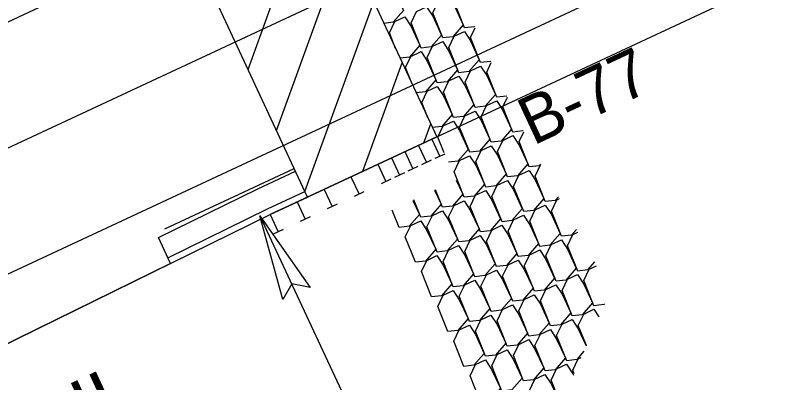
# Model space of a CAD drawing. Extents: x 2320644 to 2322941, y 921672 to 923041.
# Drawn here: x 2321563.6 to 2321644, y 922124.4 to 922163 of the extents above; entities that cross this region are included whole.
import ezdxf

# ---------------------------------------------------------------- set-up
doc = ezdxf.new("R2010")
doc.units = 0
for name, color, linetype in [('Matchline', 7, 'Continuous'), ('Prop Approach Slab', 7, 'Continuous'), ('Prop Approach Slab Hatching', 7, 'Continuous'), ('Prop Conc Shoulder Berm Gutter', 7, 'Continuous'), ('Prop EOT', 7, 'Continuous'), ('Prop Guardrail', 7, 'Continuous'), ('Prop Horizontal Alignment Tick Large', 7, 'Continuous'), ('Prop North Arrow NAD83 for Plan Sheets CELL', 7, 'Continuous'), ('Prop Structure Anchor Unit CELL', 7, 'Continuous'), ('Sheet Profile Grid Major CELL', 7, 'Continuous'), ('Sheet Profile Grid Minor CELL', 7, 'Continuous'), ('Skimmer Basin Note Both CELL', 7, 'Continuous')]:
    doc.layers.add(name, color=color, linetype=linetype)

msp = doc.modelspace()

# ---------------------------------------------------------------- linework, layer by layer
at = {"layer": 'Matchline'}
msp.add_line((2321411.134, 922078.361), (2321804.398, 922261.67), dxfattribs=at)
at = {"layer": 'Prop Approach Slab'}
for p, q in [((2321406.064, 922089.237), (2321799.328, 922272.547)), ((2321416.203, 922067.484), (2321809.467, 922250.794)), ((2321594.298, 922143.879), (2321579.089, 922176.508)), ((2321607.894, 922150.216), (2321594.298, 922143.879))]:
    msp.add_line(p, q, dxfattribs=at)
at = {"layer": 'Prop Approach Slab Hatching'}
for p, q in [((2321588.051, 922157.281), (2321595.31, 922177.214)), ((2321591.039, 922150.872), (2321598.297, 922170.805)), ((2321594.026, 922144.463), (2321601.284, 922164.396)), ((2321600.123, 922146.594), (2321604.272, 922157.987)), ((2321606.532, 922149.581), (2321607.259, 922151.578))]:
    msp.add_line(p, q, dxfattribs=at)
at = {"layer": 'Prop Conc Shoulder Berm Gutter'}
for p, q in [((2321590.381, 922142.053), (2321607.894, 922150.216)), ((2321589.087, 922144.759), (2321593.031, 922146.598)), ((2321578.628, 922139.627), (2321589.087, 922144.759)), ((2321579.896, 922136.908), (2321578.628, 922139.627)), ((2321579.896, 922136.908), (2321500.589, 922097.992))]:
    msp.add_line(p, q, dxfattribs=at)
at = {"layer": 'Prop Guardrail'}
msp.add_line((2321500.589, 922097.992), (2321590.381, 922142.053), dxfattribs=at)
at = {"layer": 'Prop Horizontal Alignment Tick Large'}
for p, q in [((2321607.894, 922150.216), (2321798.232, 922238.937)), ((2321592.685, 922182.845), (2321607.894, 922150.216))]:
    msp.add_line(p, q, dxfattribs=at)
at = {"layer": 'Prop Structure Anchor Unit CELL'}
for p, q in [((2321607.376, 922149.974), (2321590.381, 922142.053)), ((2321607.376, 922149.974), (2321608.221, 922148.161)), ((2321605.959, 922149.314), (2321606.804, 922147.501)), ((2321604.543, 922148.654), (2321605.388, 922146.841)), ((2321608.74, 922148.403), (2321607.701, 922147.92)), ((2321603.127, 922147.994), (2321603.972, 922146.181)), ((2321607.323, 922147.743), (2321606.285, 922147.259)), ((2321601.711, 922147.334), (2321602.556, 922145.521)), ((2321605.907, 922147.083), (2321604.869, 922146.599)), ((2321598.878, 922146.013), (2321599.723, 922144.201)), ((2321604.491, 922146.423), (2321603.453, 922145.939)), ((2321603.075, 922145.763), (2321602.037, 922145.279)), ((2321596.046, 922144.693), (2321596.891, 922142.88)), ((2321600.242, 922144.443), (2321599.204, 922143.959)), ((2321593.214, 922143.373), (2321594.059, 922141.56)), ((2321597.41, 922143.122), (2321596.372, 922142.639)), ((2321590.381, 922142.053), (2321591.226, 922140.24)), ((2321594.578, 922141.802), (2321593.539, 922141.318)), ((2321591.745, 922140.482), (2321590.707, 922139.998))]:
    msp.add_line(p, q, dxfattribs=at)
at = {"layer": 'Sheet Profile Grid Major CELL'}
msp.add_line((2321624.408, 922132.096), (2321624.927, 922131.292), dxfattribs=at)
for points in [[(2321602.848, 922166.455), (2321603.492, 922165.458), (2321604.411, 922163.487), (2321603.325, 922162.236), (2321602.342, 922162.127)], [(2321611.875, 922161.793), (2321611.858, 922161.772), (2321610.809, 922161.656), (2321609.752, 922164.308), (2321610.232, 922165.319)], [(2321609.103, 922164.929), (2321609.747, 922163.933), (2321610.666, 922161.962), (2321609.58, 922160.711), (2321608.531, 922160.594), (2321607.475, 922163.246), (2321608.038, 922164.433), (2321609.103, 922164.929)], [(2321606.826, 922163.868), (2321607.47, 922162.872), (2321608.389, 922160.9), (2321607.303, 922159.649), (2321606.254, 922159.533), (2321605.197, 922162.185), (2321605.761, 922163.372), (2321606.826, 922163.868)], [(2321603.57, 922159.491), (2321602.92, 922161.123), (2321603.484, 922162.31), (2321604.549, 922162.806)], [(2321604.549, 922162.806), (2321605.193, 922161.81), (2321606.111, 922159.839), (2321605.026, 922158.588), (2321604.042, 922158.479)], [(2321610.804, 922161.281), (2321611.448, 922160.285), (2321612.366, 922158.314), (2321611.281, 922157.063), (2321610.232, 922156.946), (2321609.175, 922159.598), (2321609.739, 922160.785), (2321610.804, 922161.281)], [(2321613.576, 922158.145), (2321613.558, 922158.124), (2321612.509, 922158.008), (2321611.452, 922160.659), (2321611.933, 922161.67)], [(2321608.527, 922160.22), (2321609.17, 922159.223), (2321610.089, 922157.252), (2321609.003, 922156.001), (2321607.955, 922155.885), (2321606.898, 922158.537), (2321607.462, 922159.723), (2321608.527, 922160.22)], [(2321605.271, 922155.843), (2321604.62, 922157.475), (2321605.184, 922158.662), (2321606.249, 922159.158)], [(2321606.249, 922159.158), (2321606.893, 922158.162), (2321607.812, 922156.191), (2321606.726, 922154.94), (2321605.743, 922154.83)], [(2321615.276, 922154.497), (2321615.258, 922154.476), (2321614.21, 922154.36), (2321613.153, 922157.011), (2321613.633, 922158.022)], [(2321612.504, 922157.633), (2321613.148, 922156.637), (2321614.067, 922154.665), (2321612.981, 922153.415), (2321611.932, 922153.298), (2321610.875, 922155.95), (2321611.439, 922157.137), (2321612.504, 922157.633)], [(2321610.227, 922156.572), (2321610.871, 922155.575), (2321611.79, 922153.604), (2321610.704, 922152.353), (2321609.655, 922152.237), (2321608.598, 922154.888), (2321609.162, 922156.075), (2321610.227, 922156.572)], [(2321606.971, 922152.195), (2321606.321, 922153.827), (2321606.885, 922155.014), (2321607.95, 922155.51)], [(2321607.95, 922155.51), (2321608.594, 922154.514), (2321609.512, 922152.542), (2321608.427, 922151.292), (2321607.443, 922151.182)], [(2321614.205, 922153.985), (2321614.849, 922152.989), (2321615.767, 922151.017), (2321614.682, 922149.766), (2321613.633, 922149.65), (2321612.576, 922152.302), (2321613.14, 922153.489), (2321614.205, 922153.985)], [(2321616.977, 922150.849), (2321616.959, 922150.828), (2321615.91, 922150.711), (2321614.853, 922153.363), (2321615.334, 922154.374)], [(2321611.928, 922152.923), (2321612.571, 922151.927), (2321613.49, 922149.956), (2321612.404, 922148.705), (2321611.356, 922148.588), (2321610.299, 922151.24), (2321610.863, 922152.427), (2321611.928, 922152.923)], [(2321608.672, 922148.547), (2321608.021, 922150.179), (2321608.585, 922151.366), (2321609.65, 922151.862)], [(2321609.65, 922151.862), (2321610.294, 922150.866), (2321611.213, 922148.894), (2321610.127, 922147.643), (2321609.144, 922147.534)], [(2321618.79, 922147.33), (2321618.659, 922147.18), (2321617.611, 922147.063), (2321616.554, 922149.715), (2321617.034, 922150.726)], [(2321615.905, 922150.337), (2321616.549, 922149.34), (2321617.468, 922147.369), (2321616.382, 922146.118), (2321615.333, 922146.002), (2321614.276, 922148.654), (2321614.84, 922149.84), (2321615.905, 922150.337)], [(2321613.628, 922149.275), (2321614.272, 922148.279), (2321615.191, 922146.308), (2321614.105, 922145.057), (2321613.056, 922144.94), (2321611.999, 922147.592), (2321612.563, 922148.779), (2321613.628, 922149.275)], [(2321611.351, 922148.214), (2321611.995, 922147.218), (2321612.913, 922145.246), (2321611.828, 922143.995), (2321610.779, 922143.879), (2321609.722, 922146.531), (2321610.286, 922147.717), (2321611.351, 922148.214)], [(2321617.606, 922146.689), (2321618.25, 922145.692), (2321619.168, 922143.721), (2321618.083, 922142.47), (2321617.034, 922142.354), (2321615.977, 922145.005), (2321616.541, 922146.192), (2321617.606, 922146.689)], [(2321620.688, 922143.91), (2321620.36, 922143.532), (2321619.311, 922143.415), (2321618.254, 922146.067), (2321618.818, 922147.254), (2321618.829, 922147.259)], [(2321609.95, 922145.658), (2321610.636, 922144.185), (2321609.55, 922142.934), (2321608.501, 922142.817), (2321607.774, 922144.643)], [(2321615.329, 922145.627), (2321615.972, 922144.631), (2321616.891, 922142.659), (2321615.805, 922141.409), (2321614.756, 922141.292), (2321613.7, 922143.944), (2321614.264, 922145.131), (2321615.329, 922145.627)], [(2321607.672, 922144.596), (2321608.359, 922143.123), (2321607.273, 922141.872), (2321606.224, 922141.756), (2321605.497, 922143.582)], [(2321613.051, 922144.566), (2321613.695, 922143.569), (2321614.614, 922141.598), (2321613.528, 922140.347), (2321612.479, 922140.231), (2321611.422, 922142.882), (2321611.986, 922144.069), (2321613.051, 922144.566)], [(2321605.395, 922143.535), (2321606.082, 922142.062), (2321604.996, 922140.811), (2321603.947, 922140.694), (2321603.219, 922142.52)], [(2321610.774, 922143.504), (2321611.418, 922142.508), (2321612.337, 922140.537), (2321611.251, 922139.286), (2321610.202, 922139.169), (2321609.145, 922141.821), (2321609.709, 922143.008), (2321610.774, 922143.504)], [(2321622.587, 922140.49), (2321622.06, 922139.884), (2321621.011, 922139.767), (2321619.955, 922142.419), (2321620.519, 922143.606), (2321620.788, 922143.731)], [(2321619.306, 922143.041), (2321619.95, 922142.044), (2321620.869, 922140.073), (2321619.783, 922138.822), (2321618.734, 922138.705), (2321617.677, 922141.357), (2321618.241, 922142.544), (2321619.306, 922143.041)], [(2321608.497, 922142.443), (2321609.14, 922141.446), (2321610.059, 922139.475), (2321608.974, 922138.224), (2321607.925, 922138.108), (2321606.868, 922140.759), (2321607.432, 922141.946), (2321608.497, 922142.443)], [(2321617.029, 922141.979), (2321617.673, 922140.983), (2321618.592, 922139.011), (2321617.506, 922137.761), (2321616.457, 922137.644), (2321615.4, 922140.296), (2321615.964, 922141.483), (2321617.029, 922141.979)], [(2321606.22, 922141.381), (2321606.863, 922140.385), (2321607.782, 922138.414), (2321606.696, 922137.163), (2321605.647, 922137.046), (2321604.591, 922139.698), (2321605.155, 922140.885), (2321606.22, 922141.381)], [(2321614.752, 922140.918), (2321615.395, 922139.921), (2321616.314, 922137.95), (2321615.229, 922136.699), (2321614.18, 922136.582), (2321613.123, 922139.234), (2321613.687, 922140.421), (2321614.752, 922140.918)], [(2321612.475, 922139.856), (2321613.118, 922138.86), (2321614.037, 922136.888), (2321612.951, 922135.638), (2321611.902, 922135.521), (2321610.846, 922138.173), (2321611.41, 922139.36), (2321612.475, 922139.856)], [(2321624.485, 922137.07), (2321623.761, 922136.235), (2321622.712, 922136.119), (2321621.655, 922138.771), (2321622.219, 922139.957), (2321622.746, 922140.203)], [(2321610.197, 922138.795), (2321610.841, 922137.798), (2321611.76, 922135.827), (2321610.674, 922134.576), (2321609.625, 922134.46), (2321608.568, 922137.111), (2321609.132, 922138.298), (2321610.197, 922138.795)], [(2321621.007, 922139.392), (2321621.65, 922138.396), (2321622.569, 922136.425), (2321621.484, 922135.174), (2321620.435, 922135.057), (2321619.378, 922137.709), (2321619.942, 922138.896), (2321621.007, 922139.392)], [(2321618.73, 922138.331), (2321619.373, 922137.335), (2321620.292, 922135.363), (2321619.206, 922134.112), (2321618.157, 922133.996), (2321617.101, 922136.648), (2321617.665, 922137.834), (2321618.73, 922138.331)], [(2321607.92, 922137.733), (2321608.564, 922136.737), (2321609.483, 922134.765), (2321608.397, 922133.515), (2321607.348, 922133.398), (2321606.291, 922136.05), (2321606.855, 922137.237), (2321607.92, 922137.733)], [(2321616.452, 922137.269), (2321617.096, 922136.273), (2321618.015, 922134.302), (2321616.929, 922133.051), (2321615.88, 922132.934), (2321614.823, 922135.586), (2321615.387, 922136.773), (2321616.452, 922137.269)], [(2321614.175, 922136.208), (2321614.819, 922135.212), (2321615.738, 922133.24), (2321614.652, 922131.989), (2321613.603, 922131.873), (2321612.546, 922134.525), (2321613.11, 922135.712), (2321614.175, 922136.208)], [(2321625.515, 922132.649), (2321625.461, 922132.587), (2321624.412, 922132.471), (2321623.356, 922135.122), (2321623.92, 922136.309), (2321624.704, 922136.675)], [(2321622.707, 922135.744), (2321623.351, 922134.748), (2321624.27, 922132.777), (2321623.184, 922131.526), (2321622.135, 922131.409), (2321621.078, 922134.061), (2321621.642, 922135.248), (2321622.707, 922135.744)], [(2321611.898, 922135.146), (2321612.541, 922134.15), (2321613.46, 922132.179), (2321612.375, 922130.928), (2321611.326, 922130.811), (2321610.269, 922133.463), (2321610.833, 922134.65), (2321611.898, 922135.146)], [(2321620.43, 922134.683), (2321621.074, 922133.686), (2321621.993, 922131.715), (2321620.907, 922130.464), (2321619.858, 922130.348), (2321618.801, 922132.999), (2321619.365, 922134.186), (2321620.43, 922134.683)], [(2321609.62, 922134.085), (2321610.264, 922133.089), (2321611.183, 922131.117), (2321610.097, 922129.866), (2321609.048, 922129.75), (2321607.992, 922132.402), (2321608.555, 922133.589), (2321609.62, 922134.085)], [(2321618.153, 922133.621), (2321618.796, 922132.625), (2321619.715, 922130.654), (2321618.63, 922129.403), (2321617.581, 922129.286), (2321616.524, 922131.938), (2321617.088, 922133.125), (2321618.153, 922133.621)], [(2321615.875, 922132.56), (2321616.519, 922131.563), (2321617.438, 922129.592), (2321616.352, 922128.341), (2321615.303, 922128.225), (2321614.247, 922130.877), (2321614.81, 922132.063), (2321615.875, 922132.56)], [(2321613.598, 922131.498), (2321614.242, 922130.502), (2321615.161, 922128.531), (2321614.075, 922127.28), (2321613.026, 922127.163), (2321611.969, 922129.815), (2321612.533, 922131.002), (2321613.598, 922131.498)], [(2321623.626, 922128.288), (2321622.779, 922130.413), (2321623.343, 922131.6), (2321624.408, 922132.096)], [(2321623.626, 922128.288), (2321622.779, 922130.413), (2321623.343, 922131.6), (2321624.408, 922132.096)], [(2321623.368, 922127.693), (2321622.607, 922126.816), (2321621.558, 922126.7), (2321620.502, 922129.351), (2321621.065, 922130.538), (2321622.13, 922131.035)], [(2321622.13, 922131.035), (2321622.774, 922130.038), (2321623.609, 922128.248)], [(2321611.321, 922130.437), (2321611.965, 922129.44), (2321612.884, 922127.469), (2321611.798, 922126.218), (2321610.749, 922126.102), (2321609.692, 922128.754), (2321610.256, 922129.94), (2321611.321, 922130.437)], [(2321619.853, 922129.973), (2321620.497, 922128.977), (2321621.416, 922127.005), (2321620.33, 922125.755), (2321619.281, 922125.638), (2321618.224, 922128.29), (2321618.788, 922129.477), (2321619.853, 922129.973)], [(2321617.576, 922128.912), (2321618.22, 922127.915), (2321619.139, 922125.944), (2321618.053, 922124.693), (2321617.004, 922124.577), (2321615.947, 922127.228), (2321616.511, 922128.415), (2321617.576, 922128.912)], [(2321617.576, 922128.912), (2321618.22, 922127.915), (2321619.139, 922125.944), (2321618.053, 922124.693), (2321617.004, 922124.577), (2321615.947, 922127.228), (2321616.511, 922128.415), (2321617.576, 922128.912)], [(2321615.299, 922127.85), (2321615.942, 922126.854), (2321616.861, 922124.882), (2321615.776, 922123.632), (2321614.727, 922123.515), (2321613.67, 922126.167), (2321614.234, 922127.354), (2321615.299, 922127.85)], [(2321613.021, 922126.789), (2321613.665, 922125.792), (2321614.584, 922123.821), (2321613.498, 922122.57), (2321612.449, 922122.454), (2321611.393, 922125.105), (2321611.956, 922126.292), (2321613.021, 922126.789)], [(2321622.348, 922125.337), (2321622.202, 922125.703), (2321622.766, 922126.89), (2321623.085, 922127.039)], [(2321620.942, 922122.09), (2321619.925, 922124.642), (2321620.489, 922125.829), (2321621.554, 922126.325)], [(2321621.554, 922126.325), (2321622.197, 922125.329), (2321622.274, 922125.165)], [(2321621.554, 922126.325), (2321622.197, 922125.329), (2321622.274, 922125.165)], [(2321619.276, 922125.263), (2321619.92, 922124.267), (2321620.839, 922122.296), (2321619.753, 922121.045), (2321618.704, 922120.928), (2321617.648, 922123.58), (2321618.211, 922124.767), (2321619.276, 922125.263)], [(2321619.276, 922125.263), (2321619.92, 922124.267), (2321620.839, 922122.296), (2321619.753, 922121.045), (2321618.704, 922120.928), (2321617.648, 922123.58), (2321618.211, 922124.767), (2321619.276, 922125.263)]]:
    msp.add_lwpolyline(points, dxfattribs=at)
at = {"layer": 'Sheet Profile Grid Minor CELL'}
for p, q in [((2321579.296, 922140.56), (2321592.891, 922146.897)), ((2321589.306, 922141.924), (2321612.895, 922091.381))]:
    msp.add_line(p, q, dxfattribs=at)
msp.add_lwpolyline([(2321591.708, 922133.113), (2321589.306, 922141.924), (2321594.583, 922134.4), (2321592.647, 922134.765)], close=True, dxfattribs=at)
at = {"layer": 'Skimmer Basin Note Both CELL'}
for p, q in [((2321590.093, 922142.654), (2321594.017, 922144.483)), ((2321590.381, 922142.053), (2321594.298, 922143.879)), ((2321579.614, 922137.512), (2321590.093, 922142.654)), ((2321579.896, 922136.908), (2321590.381, 922142.053))]:
    msp.add_line(p, q, dxfattribs=at)

# ---------------------------------------------------------------- texts
at = {"layer": 'Prop EOT'}
msp.add_text('B-77', height=5, rotation=25.01869, dxfattribs=at).set_placement((2321618.016, 922149.254))
at = {"layer": 'Prop North Arrow NAD83 for Plan Sheets CELL'}
msp.add_text('PROP. GUARDRAIL', height=6, rotation=24.9913, dxfattribs=at).set_placement((2321510.279, 922090.149))

doc.saveas('drawing.dxf')
